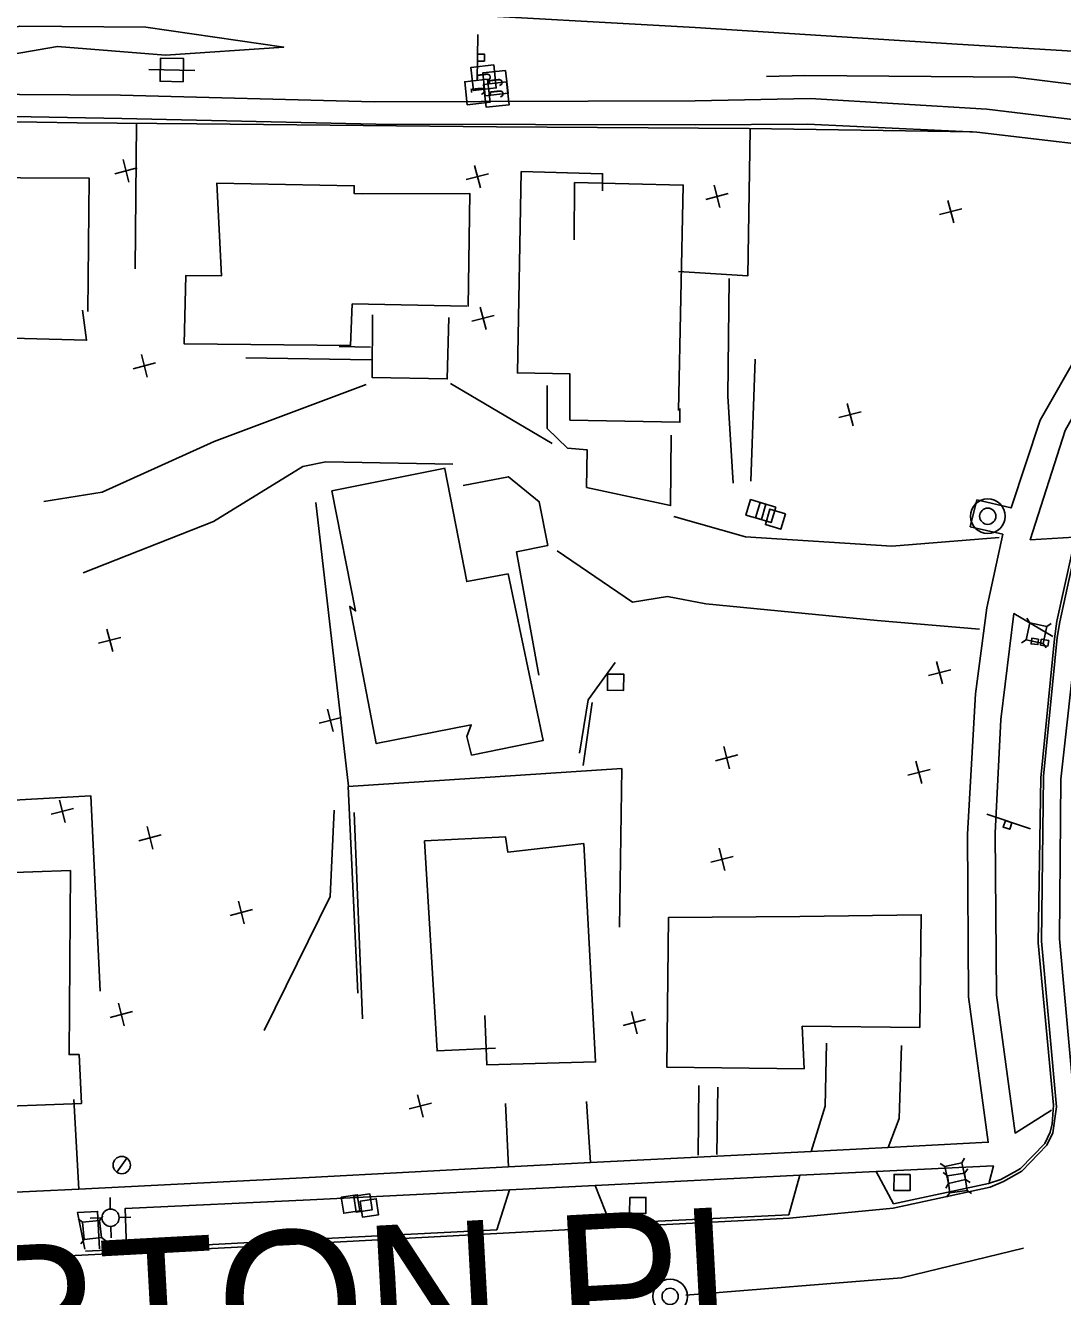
# Model space of a CAD drawing. Extents: x 4711259 to 4716401, y 890074 to 892728.
# Drawn here: x 4714553.7 to 4714778.1, y 891043.5 to 891318.6 of the extents above; entities that cross this region are included whole.
import ezdxf

# ---------------------------------------------------------------- set-up
doc = ezdxf.new("R2010")
doc.units = 0
for name, color, linetype in [('E_HY_STORM_MH', 7, 'Continuous'), ('E_RDWY_PHOTOG_Eave', 7, 'Continuous'), ('E_RDWY_PHOTOG_Fence', 7, 'Continuous'), ('E_RDWY_ROAD_Approach', 7, 'Continuous'), ('E_RDWY_ROAD_Curb', 7, 'Continuous'), ('E_RDWY_ROAD_EdgeAsph', 7, 'Continuous'), ('E_RDWY_ROAD_EdgeGravel', 7, 'Continuous'), ('E_RDWY_ROAD_NameTx', 7, 'Continuous'), ('E_RDWY_ROAD_Sidewalk', 7, 'Continuous'), ('E_RDWY_ROAD_Striping', 7, 'Continuous'), ('E_RDWY_ROAD_TBofCurb', 7, 'Continuous'), ('E_TERR_DTM_BrkLines', 7, 'Continuous'), ('E_TERR_DTM_RandomPt', 7, 'Continuous'), ('E_TRAF_SIGN_PublicSign', 7, 'Continuous'), ('E_UTIL_COMM_General', 7, 'Continuous'), ('E_UTIL_ELEC_GENERAL', 7, 'Continuous'), ('E_UTIL_ELEC_POLE', 7, 'Continuous'), ('E_UTIL_MISC_General', 7, 'Continuous'), ('E_UTIL_WTR_General', 7, 'Continuous')]:
    doc.layers.add(name, color=color, linetype=linetype)

msp = doc.modelspace()

# ---------------------------------------------------------------- linework, layer by layer
at = {"layer": 'E_HY_STORM_MH'}
for centre, radius in [((4714761.96, 891212.39), 3.75), ((4714761.96, 891212.39), 1.76), ((4714693.22, 891043.5), 3.75), ((4714693.22, 891043.5), 1.76)]:
    msp.add_circle(centre, radius, dxfattribs=at)
at = {"layer": 'E_RDWY_PHOTOG_Eave'}
for points in [[(4714567.21, 891256.67), (4714567.5, 891285.56), (4714537.7, 891285.74), (4714537.55, 891282.26), (4714537.03, 891282.46), (4714535.12, 891284.48), (4714529.51, 891284.6), (4714527.73, 891282.43), (4714514.95, 891282.43)], [(4714678.56, 891282.83), (4714678.6, 891286.53), (4714660.99, 891287), (4714660.17, 891243.4), (4714671.52, 891243.2), (4714671.52, 891233.21), (4714695.32, 891232.72), (4714695.34, 891235.74)], [(4714649.49, 891257.81), (4714649.89, 891282.23), (4714626.69, 891282.2), (4714624.84, 891282.23), (4714624.86, 891283.92), (4714595.09, 891284.48), (4714596.11, 891264.4), (4714588.39, 891264.46), (4714588.06, 891249.68), (4714624.02, 891249.34), (4714624.42, 891258.36), (4714649.25, 891257.86)], [(4714695.04, 891235.29), (4714696.07, 891284.07), (4714672.54, 891284.61), (4714672.43, 891272.2)], [(4714512.39, 891260.38), (4714537.3, 891260.29), (4714537.32, 891251.28), (4714566.92, 891250.49), (4714566.04, 891257)], [(4714644.5, 891222.81), (4714620.02, 891217.85), (4714625.15, 891191.9), (4714623.89, 891192.85), (4714629.61, 891163.18), (4714650.16, 891167.2), (4714649.19, 891164.7), (4714650.25, 891160.68), (4714665.76, 891163.85), (4714658.14, 891199.89), (4714649.19, 891198.25), (4714644.47, 891222.68)], [(4714655.44, 891097.21), (4714642.78, 891096.64), (4714640.09, 891142.09), (4714657.58, 891143.02), (4714658.12, 891139.65), (4714674.52, 891141.51), (4714677.08, 891094.27), (4714653.57, 891093.6), (4714653.08, 891104.31)], [(4714546.72, 891137.82), (4714528.54, 891136.86), (4714530.73, 891091.75), (4714541.65, 891091.77), (4714542.31, 891084.37), (4714565.8, 891085.24), (4714565.29, 891095.84), (4714563.15, 891095.86), (4714563.43, 891135.67), (4714547.03, 891135.09)], [(4714721.25, 891125.76), (4714747.57, 891126.11), (4714747.25, 891101.74), (4714721.77, 891102.01)], [(4714721.77, 891102.01), (4714722.19, 891092.79), (4714692.53, 891093.1), (4714692.88, 891125.55), (4714721.25, 891125.76)]]:
    msp.add_lwpolyline(points, dxfattribs=at)
at = {"layer": 'E_RDWY_PHOTOG_Fence'}
for points in [[(4714758.67, 891295.62), (4714710.33, 891296.3), (4714655.62, 891296.65), (4714590.81, 891297.29), (4714564.88, 891297.55), (4714503.71, 891298.54), (4714432.09, 891299.58)], [(4714577.46, 891265.97), (4714577.75, 891297.46)], [(4714710.52, 891296.08), (4714710.01, 891264.39), (4714695.04, 891265.35)], [(4714623.58, 891153.93), (4714616.55, 891215.38)], [(4714625.64, 891109.14), (4714623.56, 891153.86), (4714682.74, 891157.76), (4714682.23, 891123.4)], [(4714426.54, 891144.49), (4714443.49, 891146.04), (4714492.98, 891147.94), (4714531.88, 891149.85), (4714567.81, 891151.89), (4714569.89, 891109.55)]]:
    msp.add_lwpolyline(points, dxfattribs=at)
at = {"layer": 'E_RDWY_ROAD_Approach'}
for points in [[(4714645.32, 891255.38), (4714644.97, 891242.12), (4714628.71, 891242.43), (4714628.83, 891256)], [(4714693.47, 891229.93), (4714693.32, 891214.68), (4714675.14, 891218.61), (4714675.24, 891226.78), (4714671.01, 891227.1), (4714666.57, 891231.4), (4714666.62, 891240.7)], [(4714727.05, 891098.32), (4714726.77, 891084.71), (4714723.72, 891074.89)], [(4714740.39, 891075.71), (4714742.8, 891082.01), (4714743.28, 891097.81)], [(4714564.16, 891086.12), (4714565.21, 891066.69)], [(4714658.21, 891071.56), (4714657.59, 891085.25)], [(4714675.08, 891085.73), (4714676.01, 891072.52)], [(4714718.92, 891061.15), (4714721.32, 891069.76)], [(4714741.53, 891063.56), (4714737.8, 891070.58)], [(4714655.71, 891057.93), (4714658.42, 891066.56)], [(4714680.27, 891059.32), (4714677.01, 891067.52)]]:
    msp.add_lwpolyline(points, dxfattribs=at)
at = {"layer": 'E_RDWY_ROAD_Curb'}
msp.add_lwpolyline([(4714455.87, 891056.13), (4714463.63, 891049.06), (4714470.77, 891047.36), (4714512.4, 891049.78), (4714544.36, 891051.31), (4714563.1, 891052.26), (4714616.43, 891055.02), (4714655.73, 891057.11), (4714679.82, 891058.43), (4714719.03, 891060.42), (4714741.51, 891062.62), (4714762.51, 891067.19), (4714765.34, 891068.41), (4714769.32, 891070.63), (4714774.74, 891076.23), (4714776.06, 891078.91), (4714776.83, 891084.52), (4714773.6, 891120.39), (4714774.05, 891156.1), (4714776.99, 891186.12), (4714777.56, 891189.52), (4714780.34, 891202.47)], dxfattribs=at)
at = {"layer": 'E_RDWY_ROAD_EdgeAsph'}
msp.add_lwpolyline([(4714412.07, 891317.13), (4714421.12, 891318.22), (4714480.4, 891321.25), (4714536.91, 891324.63), (4714588.2, 891323.89), (4714641.59, 891321.38), (4714698.61, 891318.18), (4714754.2, 891314.67), (4714804.09, 891311.59), (4714810.85, 891309.49), (4714814.29, 891305.29)], dxfattribs=at)
at = {"layer": 'E_RDWY_ROAD_EdgeGravel'}
for points in [[(4714627.41, 891240.88), (4714594.51, 891228.55), (4714570.3, 891217.59), (4714557.7, 891215.57)], [(4714667.69, 891228.1), (4714645.66, 891241.1)], [(4714566.17, 891200.15), (4714594.4, 891211.26), (4714613.71, 891223.17), (4714618.71, 891224.14), (4714646.2, 891223.69)], [(4714764.41, 891207.77), (4714741.21, 891205.89), (4714709.56, 891207.94), (4714694.01, 891212.35)], [(4714760.14, 891187.93), (4714737.99, 891189.85), (4714700.96, 891193.45), (4714692.67, 891194.99), (4714685.08, 891193.81), (4714668.77, 891204.91)]]:
    msp.add_lwpolyline(points, dxfattribs=at)
at = {"layer": 'E_RDWY_ROAD_Sidewalk'}
for points in [[(4714430.5, 891303.89), (4714469.91, 891304.09), (4714519.5, 891303.9), (4714574.25, 891303.54), (4714629.16, 891302.07), (4714698.66, 891302.33), (4714723.54, 891302.84), (4714761.76, 891300.47)], [(4714759.61, 891295.53), (4714722.95, 891297.27), (4714698.65, 891297.09), (4714629.54, 891297.27), (4714574.55, 891298.45), (4714519.5, 891299.49), (4714469.75, 891299.57), (4714430.4, 891299.5)], [(4714816.5, 891296.69), (4714808.62, 891294.81), (4714802.45, 891295.59), (4714761.76, 891300.47)], [(4714759.61, 891295.53), (4714796.48, 891291.21), (4714801.58, 891290.53)], [(4714740.39, 891075.71), (4714762.07, 891076.89), (4714757.78, 891108.32), (4714757.55, 891143.53), (4714759.3, 891173.97), (4714761.75, 891192.58), (4714765.2, 891208.47), (4714758.18, 891210.11), (4714759.62, 891215.93), (4714767, 891214.2), (4714773.27, 891233.21), (4714790.74, 891263.77), (4714799.25, 891281.17), (4714793.25, 891282.77), (4714794.89, 891288.77), (4714800.82, 891287.57), (4714801.58, 891290.53)], [(4714816.03, 891285.88), (4714807.71, 891289.98), (4714802.61, 891273.83), (4714793.12, 891256.66), (4714778.72, 891230.97), (4714771.15, 891207.3), (4714780.69, 891207.86)], [(4714628.39, 891248.97), (4714621.57, 891249.1)], [(4714628.56, 891246.24), (4714601.42, 891246.68)], [(4714648.4, 891219.02), (4714658.2, 891220.94), (4714664.89, 891215.52), (4714666.73, 891206.08), (4714659.97, 891204.69), (4714664.82, 891177.96)], [(4714776.06, 891186.33), (4714767.62, 891191.33), (4714764.8, 891168.36), (4714763.59, 891143.8), (4714763.84, 891108.72), (4714767.88, 891078.87), (4714775.73, 891083.79)], [(4714699.42, 891089.15), (4714699.27, 891074.08)], [(4714703.34, 891074.26), (4714703.52, 891088.83)], [(4714459.82, 891061.41), (4714481.4, 891062.46), (4714520.09, 891064.54), (4714546.82, 891065.89), (4714565.21, 891066.69), (4714615.06, 891069.22), (4714658.21, 891071.56), (4714676.01, 891072.52), (4714723.72, 891074.89)], [(4714740.39, 891075.71), (4714723.72, 891074.89)], [(4714762.23, 891068.17), (4714763.19, 891071.79), (4714737.8, 891070.58)], [(4714721.32, 891069.76), (4714677.01, 891067.52)], [(4714721.32, 891069.76), (4714737.8, 891070.58)], [(4714677.01, 891067.52), (4714658.42, 891066.56), (4714615.32, 891064.4), (4714575.24, 891062.52), (4714575.59, 891053.96)], [(4714569.75, 891053.84), (4714569.3, 891061.92), (4714564.97, 891061.7), (4714566.52, 891053.73)]]:
    msp.add_lwpolyline(points, dxfattribs=at)
at = {"layer": 'E_RDWY_ROAD_Striping'}
msp.add_lwpolyline([(4714780.77, 891084.16), (4714777.51, 891120.9), (4714777.75, 891155.5), (4714781.25, 891186.73), (4714785.5, 891205.56), (4714797.57, 891238.22), (4714808.77, 891260.52), (4714820.56, 891283.5)], dxfattribs=at)
at = {"layer": 'E_RDWY_ROAD_TBofCurb'}
for points in [[(4714813.48, 891304.99), (4714816.67, 891296.91), (4714817.06, 891293.87), (4714816.78, 891288.8), (4714816.16, 891285.86), (4714815.48, 891283.33), (4714793.06, 891240.09), (4714781.17, 891207.95), (4714780.22, 891204.65), (4714776.92, 891189.64), (4714776.38, 891185.87), (4714773.42, 891155.74), (4714772.86, 891120.07), (4714776.18, 891084.87), (4714775.88, 891080.89), (4714775.48, 891079.03), (4714774.32, 891076.59), (4714769.02, 891071.22), (4714768.31, 891070.73), (4714764.77, 891068.82), (4714762.1, 891067.96)], [(4714741.53, 891063.56), (4714762.1, 891067.96)], [(4714680.27, 891059.32), (4714718.92, 891061.15)], [(4714566.71, 891053.31), (4714569.73, 891053.46), (4714618.6, 891056.07), (4714655.71, 891057.93)]]:
    msp.add_lwpolyline(points, dxfattribs=at)
at = {"layer": 'E_TERR_DTM_BrkLines'}
for points in [[(4714530.93, 891308.91), (4714560.6, 891314.1), (4714584, 891312.2), (4714609.61, 891313.94), (4714579.72, 891318.25), (4714552.45, 891318.5), (4714529.16, 891313.03)], [(4714808.75, 891302.39), (4714767.9, 891307.46), (4714722.36, 891307.78), (4714714.06, 891307.54)], [(4714706.84, 891219.53), (4714705.69, 891238.39), (4714706, 891263.85)], [(4714711.61, 891246.36), (4714710.71, 891219.96)], [(4714681.3, 891180.7), (4714675.49, 891172.64), (4714673.59, 891161.11)], [(4714674.36, 891158.4), (4714676.37, 891172.1)], [(4714620.49, 891148.75), (4714619.61, 891130.04), (4714605.39, 891101.1)], [(4714626.62, 891103.59), (4714624.8, 891148.22)], [(4714696.6, 891043.77), (4714743.32, 891047.53), (4714769.68, 891053.96)]]:
    msp.add_lwpolyline(points, dxfattribs=at)
at = {"layer": 'E_TERR_DTM_RandomPt'}
for p, q in [((4714576.08, 891284.73), (4714574.83, 891289.57)), ((4714577.87, 891287.78), (4714573.03, 891286.53)), ((4714653.94, 891286.49), (4714649.1, 891285.24)), ((4714652.14, 891283.44), (4714650.89, 891288.28)), ((4714703.98, 891279.18), (4714702.73, 891284.02)), ((4714705.77, 891282.23), (4714700.93, 891280.98)), ((4714754.59, 891275.89), (4714753.34, 891280.73)), ((4714756.38, 891278.94), (4714751.54, 891277.69)), ((4714655.16, 891255.83), (4714650.32, 891254.58)), ((4714653.37, 891252.78), (4714652.11, 891257.62)), ((4714580.04, 891242.52), (4714578.79, 891247.36)), ((4714581.83, 891245.56), (4714576.99, 891244.31)), ((4714732.8, 891231.95), (4714731.55, 891236.79)), ((4714734.59, 891234.99), (4714729.75, 891233.74)), ((4714572.58, 891183.09), (4714571.33, 891187.93)), ((4714574.37, 891186.13), (4714569.53, 891184.88)), ((4714753.94, 891179.16), (4714749.1, 891177.91)), ((4714752.14, 891176.11), (4714750.89, 891180.95)), ((4714620.28, 891165.79), (4714619.03, 891170.64)), ((4714622.07, 891168.84), (4714617.23, 891167.59)), ((4714706.06, 891157.68), (4714704.81, 891162.52)), ((4714707.86, 891160.72), (4714703.01, 891159.47)), ((4714747.67, 891154.54), (4714746.42, 891159.38)), ((4714749.47, 891157.59), (4714744.63, 891156.34)), ((4714562.29, 891146.07), (4714561.04, 891150.91)), ((4714564.09, 891149.11), (4714559.25, 891147.86)), ((4714583.05, 891143.39), (4714578.21, 891142.14)), ((4714581.25, 891140.35), (4714580, 891145.19)), ((4714705.06, 891135.67), (4714703.8, 891140.51)), ((4714706.85, 891138.72), (4714702.01, 891137.47)), ((4714601.03, 891124.19), (4714599.78, 891129.03)), ((4714602.83, 891127.23), (4714597.99, 891125.98)), ((4714575.09, 891102.1), (4714573.84, 891106.95)), ((4714576.88, 891105.15), (4714572.04, 891103.9)), ((4714686.09, 891100.37), (4714684.84, 891105.21)), ((4714687.88, 891103.42), (4714683.04, 891102.17)), ((4714641.58, 891085.33), (4714636.73, 891084.08)), ((4714639.78, 891082.29), (4714638.53, 891087.13))]:
    msp.add_line(p, q, dxfattribs=at)
at = {"layer": 'E_TRAF_SIGN_PublicSign'}
for p, q in [((4714651.43, 891306.67), (4714651.62, 891316.67)), ((4714652.28, 891311.66), (4714652.28, 891311.66)), ((4714761.72, 891147.86), (4714771.21, 891144.71)), ((4714766.23, 891145.57), (4714766.23, 891145.57))]:
    msp.add_line(p, q, dxfattribs=at)
for points in [[(4714651.51, 891310.92), (4714653.01, 891310.89), (4714653.04, 891312.39), (4714651.54, 891312.42)], [(4714765.76, 891146.52), (4714765.28, 891145.1), (4714766.71, 891144.62), (4714767.18, 891146.05)]]:
    msp.add_lwpolyline(points, close=True, dxfattribs=at)
at = {"layer": 'E_UTIL_COMM_General'}
for points in [[(4714713.96, 891215.01), (4714712.97, 891211.66), (4714709.61, 891212.65), (4714710.61, 891216)], [(4714716.06, 891214.37), (4714715.07, 891211.02), (4714711.71, 891212.01), (4714712.71, 891215.36)], [(4714718.17, 891212.94), (4714717.17, 891209.58), (4714713.82, 891210.57), (4714714.81, 891213.93)], [(4714679.67, 891178.23), (4714683.17, 891178.2), (4714683.14, 891174.7), (4714679.64, 891174.73)], [(4714745.17, 891069.9), (4714745.14, 891066.4), (4714741.64, 891066.43), (4714741.67, 891069.93)], [(4714622.05, 891064.98), (4714625.51, 891065.51), (4714626.03, 891062.05), (4714622.57, 891061.52)], [(4714624.75, 891065.19), (4714628.21, 891065.72), (4714628.73, 891062.26), (4714625.27, 891061.73)], [(4714626.14, 891064.12), (4714629.6, 891064.65), (4714630.12, 891061.19), (4714626.66, 891060.66)], [(4714684.48, 891064.95), (4714687.98, 891064.92), (4714687.95, 891061.42), (4714684.45, 891061.45)]]:
    msp.add_lwpolyline(points, close=True, dxfattribs=at)
at = {"layer": 'E_UTIL_ELEC_GENERAL'}
for points in [[(4714655.04, 891310.08), (4714655.6, 891305.11), (4714650.64, 891304.54), (4714650.07, 891309.51)], [(4714657.62, 891308.9), (4714658.19, 891303.93), (4714653.22, 891303.36), (4714652.65, 891308.33)], [(4714653.72, 891307.01), (4714654.29, 891302.04), (4714649.32, 891301.47), (4714648.75, 891306.44)], [(4714657.81, 891306.44), (4714658.38, 891301.47), (4714653.41, 891300.9), (4714652.84, 891305.87)]]:
    msp.add_lwpolyline(points, close=True, dxfattribs=at)
at = {"layer": 'E_UTIL_ELEC_POLE'}
msp.add_line((4714590.37, 891308.9), (4714580.38, 891309.1), dxfattribs=at)
msp.add_lwpolyline([(4714587.83, 891306.45), (4714582.83, 891306.55), (4714582.93, 891311.55), (4714587.92, 891311.45)], close=True, dxfattribs=at)
at = {"layer": 'E_UTIL_MISC_General'}
for points in [[(4714772.96, 891185.81), (4714771.47, 891185.98), (4714771.33, 891184.76), (4714772.82, 891184.59)], [(4714773.35, 891184.49), (4714774.95, 891184.23), (4714775.15, 891185.48), (4714773.55, 891185.74)]]:
    msp.add_lwpolyline(points, close=True, dxfattribs=at)
at = {"layer": 'E_UTIL_WTR_General'}
for p, q in [((4714771.04, 891189.3), (4714770.4, 891190.29)), ((4714774.71, 891188.53), (4714775.7, 891189.17)), ((4714770.27, 891185.63), (4714769.28, 891184.99)), ((4714773.93, 891184.86), (4714774.58, 891183.87)), ((4714575.64, 891073.46), (4714573.45, 891070.42)), ((4714752.66, 891071.62), (4714751.66, 891072.25)), ((4714756.32, 891072.45), (4714756.95, 891073.44)), ((4714756.93, 891070.17), (4714757.64, 891071.11)), ((4714753.22, 891069.63), (4714752.28, 891070.33)), ((4714757.15, 891068.79), (4714758.14, 891068.16)), ((4714753.49, 891067.96), (4714752.86, 891066.96)), ((4714753.76, 891065.92), (4714753.05, 891064.97)), ((4714757.47, 891066.45), (4714758.41, 891065.75)), ((4714572.06, 891062.42), (4714572, 891064.91)), ((4714566.01, 891059.55), (4714565.09, 891060.28)), ((4714570.23, 891060.5), (4714567.73, 891060.44)), ((4714569.73, 891059.97), (4714570.47, 891060.9)), ((4714573.98, 891060.59), (4714576.48, 891060.65)), ((4714572.15, 891058.67), (4714572.21, 891056.17)), ((4714566.43, 891055.82), (4714565.7, 891054.9)), ((4714570.16, 891056.25), (4714571.08, 891055.51))]:
    msp.add_line(p, q, dxfattribs=at)
for points in [[(4714773.93, 891184.86), (4714770.27, 891185.63), (4714771.04, 891189.3), (4714774.71, 891188.53)], [(4714752.66, 891071.62), (4714756.32, 891072.45), (4714757.15, 891068.79), (4714753.49, 891067.96)], [(4714753.22, 891069.63), (4714756.93, 891070.17), (4714757.47, 891066.45), (4714753.76, 891065.92)], [(4714569.73, 891059.97), (4714570.16, 891056.25), (4714566.43, 891055.82), (4714566.01, 891059.55)]]:
    msp.add_lwpolyline(points, close=True, dxfattribs=at)
for centre in [(4714574.54, 891071.94), (4714572.1, 891060.54)]:
    msp.add_circle(centre, 1.87, dxfattribs=at)

# ---------------------------------------------------------------- texts
at = {"layer": 'E_RDWY_ROAD_NameTx'}
msp.add_text('OVERTON PL.', height=30.8399, rotation=3.1051, dxfattribs=at).set_placement((4714454.1, 891018.41))
at = {"layer": 'E_UTIL_ELEC_GENERAL'}
for p in [(4714654.49, 891306.64), (4714653.17, 891303.58), (4714657.07, 891305.47), (4714657.27, 891303)]:
    msp.add_text('J', height=3, rotation=96.5293, dxfattribs=at).set_placement(p)

doc.saveas('drawing.dxf')
